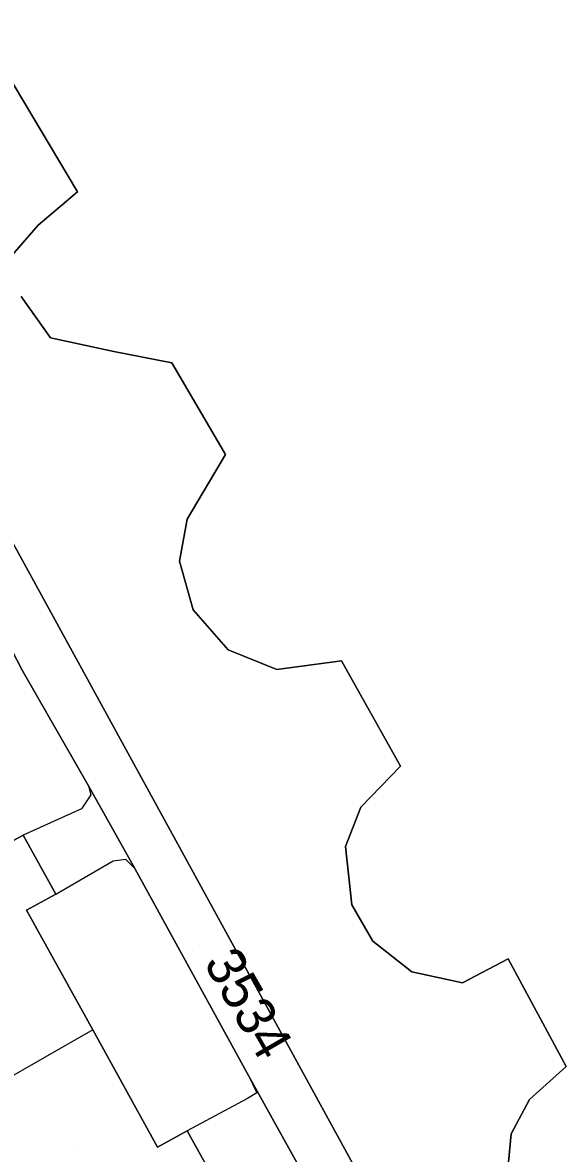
# Model space of a CAD drawing. Extents: x -262715 to -259381, y -1237238 to -1231182.
# Drawn here: x -261527.1 to -261499.2, y -1235867.1 to -1235808.7 of the extents above; entities that cross this region are included whole.
import ezdxf

# ---------------------------------------------------------------- set-up
doc = ezdxf.new("R2010")
doc.units = 0
for name, color, linetype in [('body_kn', 7, 'Continuous'), ('kladpar_druhypozemkov', 7, 'Continuous'), ('kladpar_hranice', 7, 'Continuous'), ('kladpar_parcelnecisla', 7, 'Continuous'), ('kladpar_plochy', 7, 'Continuous'), ('zappar_hrandruhpozemk', 7, 'Continuous')]:
    doc.layers.add(name, color=color, linetype=linetype)

msp = doc.modelspace()

# ---------------------------------------------------------------- linework, layer by layer
at = {"layer": 'body_kn'}
for p, q in [((-261524.28, -1235817.46), (-261524.28, -1235817.46)), ((-261526.3, -1235819.18), (-261526.3, -1235819.18)), ((-261525.67, -1235824.99), (-261525.67, -1235824.99)), ((-261522.4, -1235825.7), (-261522.4, -1235825.7)), ((-261519.41, -1235826.28), (-261519.41, -1235826.28)), ((-261516.63, -1235831.02), (-261516.63, -1235831.02)), ((-261518.62, -1235834.36), (-261518.62, -1235834.36)), ((-261519.01, -1235836.51), (-261519.01, -1235836.51)), ((-261518.3, -1235839.03), (-261518.3, -1235839.03)), ((-261516.5, -1235841.1), (-261516.5, -1235841.1)), ((-261513.99, -1235842.1), (-261513.99, -1235842.1)), ((-261510.65, -1235841.66), (-261510.65, -1235841.66)), ((-261507.6, -1235847.09), (-261507.6, -1235847.09)), ((-261523.71, -1235848.1), (-261523.71, -1235848.1)), ((-261523.71, -1235848.1), (-261523.71, -1235848.1)), ((-261523.58, -1235848.57), (-261523.58, -1235848.57)), ((-261524.06, -1235849.3), (-261524.06, -1235849.3)), ((-261509.65, -1235849.21), (-261509.65, -1235849.21)), ((-261527.08, -1235850.65), (-261527.08, -1235850.65)), ((-261510.43, -1235851.23), (-261510.43, -1235851.23)), ((-261522.44, -1235851.98), (-261522.44, -1235851.98)), ((-261521.8, -1235851.89), (-261521.8, -1235851.89)), ((-261521.32, -1235852.38), (-261521.32, -1235852.38)), ((-261525.39, -1235853.69), (-261525.39, -1235853.69)), ((-261525.39, -1235853.69), (-261525.39, -1235853.69)), ((-261510.11, -1235854.24), (-261510.11, -1235854.24)), ((-261526.9, -1235854.53), (-261526.9, -1235854.53)), ((-261509.03, -1235856.12), (-261509.03, -1235856.12)), ((-261502.04, -1235857.03), (-261502.04, -1235857.03)), ((-261507.02, -1235857.7), (-261507.02, -1235857.7)), ((-261504.4, -1235858.27), (-261504.4, -1235858.27)), ((-261523.48, -1235860.7), (-261523.48, -1235860.7)), ((-261523.48, -1235860.7), (-261523.48, -1235860.7)), ((-261515.42, -1235863.08), (-261515.42, -1235863.08)), ((-261515.42, -1235863.08), (-261515.42, -1235863.08)), ((-261515.49, -1235864.24), (-261515.49, -1235864.24)), ((-261515.02, -1235863.94), (-261515.02, -1235863.94)), ((-261500.93, -1235864.29), (-261500.93, -1235864.29)), ((-261518.61, -1235865.9), (-261518.61, -1235865.9)), ((-261501.88, -1235866.06), (-261501.88, -1235866.06)), ((-261520.14, -1235866.75), (-261520.14, -1235866.75))]:
    msp.add_line(p, q, dxfattribs=at)
at = {"layer": 'kladpar_druhypozemkov'}
for p, q in [((-261517.98, -1235856.36), (-261517.98, -1235856.36)), ((-261524.26, -1235866.8), (-261524.26, -1235866.8))]:
    msp.add_line(p, q, dxfattribs=at)
at = {"layer": 'kladpar_hranice'}
for points in [[(-261502.63, -1235766.42), (-261501.35, -1235768.52), (-261504.04, -1235769.74), (-261513.86, -1235775.17), (-261531.1, -1235784.06), (-261546.32, -1235792.29), (-261547.93, -1235793.44), (-261548.56, -1235795.63), (-261548.57, -1235797.69), (-261547.79, -1235799.69), (-261542.76, -1235808.22), (-261535.17, -1235821.81), (-261498.26, -1235889.12)], [(-261498.26, -1235889.12), (-261535.17, -1235821.81), (-261542.76, -1235808.22), (-261543.39, -1235804.72), (-261543.59, -1235800.49), (-261542.63, -1235796.5), (-261540.31, -1235792.68), (-261537.27, -1235788.94), (-261531.1, -1235784.06), (-261513.86, -1235775.17), (-261510.09, -1235774), (-261505, -1235773.97), (-261500.49, -1235774.67), (-261495.05, -1235778.21)], [(-261559.12, -1235793.53), (-261555.91, -1235799.33), (-261551, -1235800.67), (-261550.29, -1235800.56), (-261549.74, -1235801.02), (-261543.1, -1235812.84), (-261541.25, -1235816.29), (-261537.66, -1235823.03), (-261535.2, -1235827.23), (-261529.04, -1235838.47), (-261527.14, -1235842.14), (-261523.71, -1235848.1), (-261521.32, -1235852.38), (-261515.42, -1235863.08), (-261512.94, -1235867.58)], [(-261512.94, -1235867.58), (-261515.42, -1235863.08), (-261521.32, -1235852.38), (-261523.71, -1235848.1), (-261527.14, -1235842.14), (-261529.04, -1235838.47), (-261535.2, -1235827.23), (-261537.66, -1235823.03), (-261541.25, -1235816.29), (-261543.1, -1235812.84), (-261549.74, -1235801.02)], [(-261527.77, -1235820.87), (-261526.3, -1235819.18), (-261524.28, -1235817.46), (-261528.47, -1235810.45)], [(-261528.47, -1235810.45), (-261524.28, -1235817.46), (-261526.3, -1235819.18), (-261527.77, -1235820.87)], [(-261502.07, -1235868.08), (-261501.88, -1235866.06), (-261500.93, -1235864.29), (-261499.04, -1235862.59), (-261502.04, -1235857.03), (-261504.4, -1235858.27), (-261507.02, -1235857.7), (-261509.03, -1235856.12), (-261510.11, -1235854.24), (-261510.43, -1235851.23), (-261509.65, -1235849.21), (-261507.6, -1235847.09), (-261510.65, -1235841.66), (-261513.99, -1235842.1), (-261516.5, -1235841.1), (-261518.3, -1235839.03), (-261519.01, -1235836.51), (-261518.62, -1235834.36), (-261516.63, -1235831.02), (-261519.41, -1235826.28), (-261522.4, -1235825.7), (-261525.67, -1235824.99), (-261527.18, -1235822.87)], [(-261527.18, -1235822.87), (-261525.67, -1235824.99), (-261522.4, -1235825.7), (-261519.41, -1235826.28), (-261516.63, -1235831.02), (-261518.62, -1235834.36), (-261519.01, -1235836.51), (-261518.3, -1235839.03), (-261516.5, -1235841.1), (-261513.99, -1235842.1), (-261510.65, -1235841.66), (-261507.6, -1235847.09), (-261509.65, -1235849.21), (-261510.43, -1235851.23), (-261510.11, -1235854.24), (-261509.03, -1235856.12), (-261507.02, -1235857.7), (-261504.4, -1235858.27), (-261502.04, -1235857.03), (-261499.04, -1235862.59), (-261500.93, -1235864.29), (-261501.88, -1235866.06), (-261502.07, -1235868.08)], [(-261530.63, -1235847.79), (-261528.59, -1235851.48), (-261527.08, -1235850.65), (-261525.39, -1235853.69), (-261526.9, -1235854.53), (-261523.48, -1235860.7), (-261520.14, -1235866.75), (-261518.61, -1235865.9), (-261516.91, -1235868.97), (-261518.44, -1235869.81), (-261516.4, -1235873.51), (-261527.23, -1235879.71), (-261529.53, -1235875.61), (-261530.5, -1235873.86), (-261534.38, -1235866.93), (-261538.16, -1235860.17), (-261539.19, -1235858.33), (-261541.59, -1235854.05), (-261534.84, -1235850.15), (-261530.63, -1235847.79)], [(-261516.91, -1235868.97), (-261518.61, -1235865.9), (-261520.14, -1235866.75), (-261523.48, -1235860.7), (-261526.9, -1235854.53), (-261525.39, -1235853.69), (-261527.08, -1235850.65), (-261528.59, -1235851.48)]]:
    msp.add_lwpolyline(points, dxfattribs=at)
at = {"layer": 'kladpar_plochy'}
for points in [[(-261504.04, -1235769.74), (-261513.86, -1235775.17), (-261531.1, -1235784.06), (-261546.32, -1235792.29), (-261547.93, -1235793.44), (-261548.56, -1235795.63), (-261548.57, -1235797.69), (-261547.79, -1235799.69), (-261542.76, -1235808.22), (-261535.17, -1235821.81), (-261498.26, -1235889.12)], [(-261498.26, -1235889.12), (-261535.17, -1235821.81), (-261542.76, -1235808.22), (-261543.39, -1235804.72), (-261543.59, -1235800.49), (-261542.63, -1235796.5), (-261540.31, -1235792.68), (-261537.27, -1235788.94), (-261531.1, -1235784.06), (-261513.86, -1235775.17), (-261510.09, -1235774), (-261505, -1235773.97), (-261500.49, -1235774.67), (-261495.05, -1235778.21)], [(-261549.74, -1235801.02), (-261543.1, -1235812.84), (-261541.25, -1235816.29), (-261537.66, -1235823.03), (-261535.2, -1235827.23), (-261529.04, -1235838.47), (-261527.14, -1235842.14), (-261523.71, -1235848.1), (-261521.32, -1235852.38), (-261515.42, -1235863.08), (-261512.94, -1235867.58)], [(-261512.94, -1235867.58), (-261515.42, -1235863.08), (-261521.32, -1235852.38), (-261523.71, -1235848.1), (-261527.14, -1235842.14), (-261529.04, -1235838.47), (-261535.2, -1235827.23), (-261537.66, -1235823.03), (-261541.25, -1235816.29), (-261543.1, -1235812.84), (-261549.74, -1235801.02)], [(-261527.77, -1235820.87), (-261526.3, -1235819.18), (-261524.28, -1235817.46), (-261528.47, -1235810.45)], [(-261528.47, -1235810.45), (-261524.28, -1235817.46), (-261526.3, -1235819.18), (-261527.77, -1235820.87)], [(-261502.07, -1235868.08), (-261501.88, -1235866.06), (-261500.93, -1235864.29), (-261499.04, -1235862.59), (-261502.04, -1235857.03), (-261504.4, -1235858.27), (-261507.02, -1235857.7), (-261509.03, -1235856.12), (-261510.11, -1235854.24), (-261510.43, -1235851.23), (-261509.65, -1235849.21), (-261507.6, -1235847.09), (-261510.65, -1235841.66), (-261513.99, -1235842.1), (-261516.5, -1235841.1), (-261518.3, -1235839.03), (-261519.01, -1235836.51), (-261518.62, -1235834.36), (-261516.63, -1235831.02), (-261519.41, -1235826.28), (-261522.4, -1235825.7), (-261525.67, -1235824.99), (-261527.18, -1235822.87)], [(-261527.18, -1235822.87), (-261525.67, -1235824.99), (-261522.4, -1235825.7), (-261519.41, -1235826.28), (-261516.63, -1235831.02), (-261518.62, -1235834.36), (-261519.01, -1235836.51), (-261518.3, -1235839.03), (-261516.5, -1235841.1), (-261513.99, -1235842.1), (-261510.65, -1235841.66), (-261507.6, -1235847.09), (-261509.65, -1235849.21), (-261510.43, -1235851.23), (-261510.11, -1235854.24), (-261509.03, -1235856.12), (-261507.02, -1235857.7), (-261504.4, -1235858.27), (-261502.04, -1235857.03), (-261499.04, -1235862.59), (-261500.93, -1235864.29), (-261501.88, -1235866.06), (-261502.07, -1235868.08)], [(-261516.91, -1235868.97), (-261518.61, -1235865.9), (-261520.14, -1235866.75), (-261523.48, -1235860.7), (-261526.9, -1235854.53), (-261525.39, -1235853.69), (-261527.08, -1235850.65), (-261528.59, -1235851.48)]]:
    msp.add_lwpolyline(points, dxfattribs=at)
msp.add_lwpolyline([(-261530.63, -1235847.79), (-261528.59, -1235851.48), (-261527.08, -1235850.65), (-261525.39, -1235853.69), (-261526.9, -1235854.53), (-261523.48, -1235860.7), (-261520.14, -1235866.75), (-261518.61, -1235865.9), (-261516.91, -1235868.97), (-261518.44, -1235869.81), (-261516.4, -1235873.51), (-261527.23, -1235879.71), (-261529.53, -1235875.61), (-261530.5, -1235873.86), (-261534.38, -1235866.93), (-261538.16, -1235860.17), (-261539.19, -1235858.33), (-261541.59, -1235854.05), (-261534.84, -1235850.15)], close=True, dxfattribs=at)
at = {"layer": 'zappar_hrandruhpozemk'}
for p, q in [((-261524.06, -1235849.3), (-261527.08, -1235850.65)), ((-261525.39, -1235853.69), (-261522.44, -1235851.98)), ((-261523.48, -1235860.7), (-261534.38, -1235866.93)), ((-261515.49, -1235864.24), (-261518.61, -1235865.9))]:
    msp.add_line(p, q, dxfattribs=at)
for points in [[(-261523.71, -1235848.1), (-261523.58, -1235848.57), (-261524.06, -1235849.3)], [(-261522.44, -1235851.98), (-261521.8, -1235851.89), (-261521.32, -1235852.38)], [(-261515.42, -1235863.08), (-261515.02, -1235863.94), (-261515.49, -1235864.24)]]:
    msp.add_lwpolyline(points, dxfattribs=at)

# ---------------------------------------------------------------- texts
at = {"layer": 'kladpar_parcelnecisla'}
msp.add_text('3534', height=2, rotation=300, dxfattribs=at).set_placement((-261517.791, -1235857.242))

doc.saveas('drawing.dxf')
